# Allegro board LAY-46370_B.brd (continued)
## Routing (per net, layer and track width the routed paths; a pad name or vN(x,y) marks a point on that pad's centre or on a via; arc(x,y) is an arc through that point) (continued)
I2C3_SCL_3V3: length 235.3
  TOP w0.109: v1(31.41,22.55) 30.83,21.97 R291.1 ; U5.8 v1(181.52,100.89) 181.98,100.43 R13.2 182.23,100.09 182.42,99.9 185.02,99.9 187.05,97.88 J21.5
  L6_IN2 w0.114: v1(181.52,100.89) 181.44,100.89 181.08,101.25 177.1,101.25 172.78,96.94 172.78,33.55 170.72,31.48 170.72,31.01 v1(171.19,30.54)
  BOTTOM w0.109: v1(171.19,30.54) 169.63,28.98 121.7,28.98 114.5,21.77 81.51,21.77 80.2,23.08 65.06,23.08 63.74,21.76 32.2,21.76 v1(31.41,22.55)
I2C3_SDA: length 258.8
  TOP w0.102: v1(109.03,117.81) 109.03,125.05 v1(108.97,125.11) R171.2 ; v1(183.15,90.33) 182.83,90.01 R307.1 ; R161.2 85.33,125.67 v1(85.33,125.07) ; R197.1 v1(185.54,31.71)
  TOP w0.109: U5.5 178.94,100.49 v1(178.39,99.93) 177.82,99.37 R10.2 176.95,98.59 176.57,98.21 174.83,98.21 TP8.1 ; v1(101.97,58.32) 101.75,58.32 101.42,58.64 J3.63
  L6_IN2 w0.114: v1(101.97,58.32) 101.95,58.32 101.44,58.83 101.44,65.07 106.75,70.38 106.75,94.49 107.86,95.6 107.86,116.64 v1(109.03,117.81) ; v1(185.54,31.71) 184.88,32.37 184.88,88.6 v1(183.15,90.33) 183.15,97.2 182,98.35 179.98,98.35 v1(178.39,99.93)
  BOTTOM w0.109: v1(109.03,117.81) 109.21,117.81 109.59,117.44 165.61,117.44 178.86,104.2 178.86,100.4 v1(178.39,99.93) ; v1(108.97,125.11) 108.02,126.06 88.4,126.06 86.84,124.51 85.9,124.51 v1(85.33,125.07)
I2C3_SDA_3V3: length 240.6
  TOP w0.109: J21.3 191.9,100.42 193.01,99.3 193.01,97.27 192.75,97 184.01,97 182.23,98.78 R14.2 v1(181.57,100.01) 181.09,100.49 U5.7 ; R292.1 v1(32.37,22.49)
  L6_IN2 w0.114: v1(171.21,31.25) 173.25,33.3 173.25,96.86 177.3,100.91 180.66,100.91 v1(181.57,100.01)
  BOTTOM w0.109: v1(32.37,22.49) 32.82,22.04 63.33,22.04 64.67,23.38 80.46,23.38 81.74,22.1 114.34,22.1 121.61,29.37 169.32,29.37 v1(171.21,31.25)
I2C4_SCL: length 45
  TOP w0.109: v1(101.97,58.93) 101.82,59.07 J3.65
  L6_IN2 w0.114: v1(110.82,95.92) 107.12,92.22 107.12,70.23 101.82,64.93 101.82,59.07 v1(101.97,58.93)
  BOTTOM w0.109: U6.2 111.23,95.51 v1(110.82,95.92) R16.2
I2C4_SDA: length 45.2
  TOP w0.109: v1(102.59,58.91) 102.59,58.95 102.08,59.46 102.08,59.76 102.22,59.9 J3.67
  L6_IN2 w0.114: v1(111.63,95.89) 107.45,91.7 107.45,70.1 102.18,64.83 102.18,59.35 102.59,58.93 v1(102.59,58.91)
  BOTTOM w0.109: U6.3 v1(111.63,95.89) 111.63,96.3 R17.2
I2C5_SCL: length 15.7
  L6_IN2 w0.114: v1(110.45,87.44) 110.45,91.82 112.95,94.32 112.95,95.91 v1(112.71,96.15)
  BOTTOM w0.102: v1(110.45,87.44) 110.93,87.44 111.21,87.16 TP9.1 111.07,86.96 U52.11
  BOTTOM w0.109: R18.2 112.78,96.22 v1(112.71,96.15) 112.7,96.15 112.03,95.48 U6.4
I2C5_SCL_3V3: length 107.2
  TOP w0.109: v1(138.61,95.18) 138.61,99.55 157.24,118.18 190.66,118.18 196.84,124.36 196.84,127.1 R221.1
  BOTTOM w0.109: v1(138.61,95.18) 132.09,95.18 126.94,90.03 113.46,90.03 113.29,90.2 113.29,91.16 113.06,91.39 R22.2 112.03,92 U6.8
I2C5_SDA: length 16.2
  L6_IN2 w0.114: v1(108.17,87.76) 108.17,90.22 112.48,94.53 v1(112.48,95.31)
  BOTTOM w0.102: v1(108.17,87.76) 108.59,87.33 TP10.1 108.59,86.1 109.57,85.11 U52.8 ; U6.5 112.43,95.26 v1(112.48,95.31)
  BOTTOM w0.109: v1(112.48,95.31) 113.23,95.31 113.97,96.05 R19.2
I2C5_SDA_3V3: length 108.3
  TOP w0.109: R222.1 197.2,129.32 197.2,124.3 190.73,117.83 157.29,117.83 139.32,99.86 v1(139.32,95.2)
  BOTTOM w0.109: v1(139.32,95.2) 138.9,95.62 132.01,95.62 127.78,91.39 R23.2 112.43,92.78 U6.7
ILIM_5V_VBUS: length 2.2
  TOP w0.109: U11.6 32.59,20.73 TP20.1
ILIM_5V_VBUS1: length 1.7
  TOP w0.203: TP29.1 45.27,28.96 U17.6
IOEXP_NINT: length 1.8
  TOP w0.102: U1.22 182.15,88.41 R308.2
IOEXP_SCL: length 1.8
  TOP w0.102: R306.2 183.65,88.56 U1.19
IOEXP_SDA: length 1.8
  TOP w0.102: R307.2 183.15,88.52 U1.20
JTAG_MOD: length 6
  TOP w0.102: J1.66 v1(83.89,111.74) 84.52,112.37 84.52,115.13 TP122.1
  BOTTOM w0.102: v1(83.89,111.74) 83.85,111.78 R313.1
JTAG_RESET: length 118.6
  TOP w0.109: J24.10 18.68,133.14 D23.C 16.36,132.39 16.76,131.98 R245.2 ; D26.C 20.83,28.58 v1(20.58,28.83)
  L6_IN2 w0.114: J24.10 20.66,133.62 22.79,133.62 25.04,131.37 25.04,119.19 25.52,118.71 25.52,74.62 25.04,74.14 25.04,47.86 20.58,43.41 v1(20.58,28.83)
JTAG_TCK: length 134.7
  TOP w0.109: v1(16.09,83.55) 17.06,84.53 55.59,84.53 69.63,98.57 69.63,112.25 73.96,116.59 84.52,116.59 85.19,115.92 85.19,112.46 84.29,111.56 J1.68
  L6_IN2 w0.114: v1(16.09,83.55) 15.96,83.42 15.96,54.73 11.64,50.41 10.36,50.41 v1(9.93,49.98)
  BOTTOM w0.109: v1(9.93,49.98) 9.52,49.57 U8.2
JTAG_TDI: length 132.6
  TOP w0.109: v1(16.78,83.52) 17.32,84.06 55.65,84.06 69.92,98.32 69.92,112.11 74.1,116.29 81.87,116.29 83.4,114.76 83.4,111.32 83.49,111.24 J1.64
  L6_IN2 w0.114: v1(16.78,83.52) 16.41,83.15 16.41,54.62 9.83,48.04 v1(9.83,47.96)
  BOTTOM w0.109: U8.5 9.64,48.16 v1(9.83,47.96)
JTAG_TDO: length 138
  TOP w0.109: J1.62 83.1,110.66 83.1,111.06 83.13,111.1 83.13,114.57 81.66,116.04 74.36,116.04 70.19,111.87 70.19,98.15 55.76,83.72 18.35,83.72 v1(18.09,83.46)
  L6_IN2 w0.114: v1(18.09,83.46) 18.04,83.46 17.91,83.34 17.91,53.87 10.56,46.51 v1(10.38,46.51)
  BOTTOM w0.109: U8.10 7.12,49.17 6.56,48.61 6.56,47.79 8.15,46.19 10.06,46.19 v1(10.38,46.51)
JTAG_TMS: length 134.7
  TOP w0.109: v1(17.46,83.49) 17.46,83.32 17.81,82.97 18.45,82.97 18.9,83.43 55.91,83.43 70.46,97.98 70.46,111.73 74.47,115.74 81.54,115.74 82.88,114.4 82.88,111.24 82.69,111.05 J1.60
  L6_IN2 w0.114: v1(10.43,47.93) 11.5,47.93 17.46,53.89 17.46,82.67 17.46,82.67 v1(17.46,83.49)
  BOTTOM w0.109: U8.7 8.03,47.26 8.39,46.91 9.4,46.91 v1(10.43,47.93)
LD1_I2C_SCL: length 2.7
  TOP w0.203: R61.2 62.06,31.48 60.39,33.15 U14.B1
LD1_I2C_SDA: length 2.4
  TOP w0.203: U14.C1 60.5,33.55 61.46,32.58 R62.2
LD1_NINT: length 25.1
  TOP w0.109: R60.2 41.45,27.34 R63.2 41.46,27.36 v1(41.46,28.1)
  TOP w0.203: v1(61.02,33.84) 60.91,33.95 U14.D1
  BOTTOM w0.109: v1(41.46,28.1) 42.92,29.56 46.4,29.56 47.08,28.88 53.79,28.88 58.74,33.84 v1(61.02,33.84)
LED0/CFG_EXT: length 7.9
  TOP w0.102: R86.2 R92.1
  TOP w0.109: R92.1 96.14,34.67 96.25,34.57 96.25,32.46 98.65,30.06 U23.32
LED1/CFGLDO0: length 43
  TOP w0.109: C82.1 R94.1 v1(96.2,31.7) 96.36,31.7 98.41,29.66 U23.33
  L6_IN2 w0.114: v1(96.2,31.7) 96.6,31.31 96.6,29.94 95.34,28.69 95.34,13.75 104.82,4.27 107.5,4.27 J8.14
LED2/CFGLDO1: length 36.2
  TOP w0.109: C83.1 R87.2 ; C83.1 R93.1 ; C83.1 v1(96.08,30.26) 96.63,29.71 97.76,29.71 98.21,29.26 U23.34
  L6_IN2 w0.114: J8.12 98.93,3.13 98.93,9.52 94.94,13.51 94.94,29.11 v1(96.08,30.26)
LVDS0_CLK_N: length 70.5
  TOP w0.091: J15.A2 139.24,133.05 138.91,133.38 138.91,133.66 139.05,133.81 139.98,133.81 142.13,131.66 142.13,127.06 141.89,126.82 U40.10 U40.1 141.89,125.36 142.13,125.12 142.13,124.69 139.73,122.3 132.62,122.3 v1(132.52,122.4) ; v1(104.34,106.25) 104.12,106.25 103.87,106.5 103.87,106.93 103.93,106.99 J2.47
  L3_IN1 w0.084: v1(104.34,106.25) 104.23,106.14 103.92,106.14 103.79,106.01 103.66,105.87 103.66,104.78 106.26,102.18 118.36,102.18 134.06,117.88 134.06,121.4 133.16,122.3 132.64,122.3 132.54,122.4 v1(132.52,122.4)
LVDS0_CLK_P: length 70.7
  TOP w0.091: v1(132.54,121.81) 132.54,121.83 132.74,122.03 139.84,122.03 142.39,124.58 U40.2 U40.9 142.39,131.77 140.09,134.07 138.94,134.07 138.63,133.76 138.63,133.28 138.44,133.08 J15.A3 ; v1(104.37,105.66) 104.09,105.66 103.6,106.15 103.6,106.93 103.53,106.99 J2.45
  L3_IN1 w0.084: v1(132.54,121.81) 132.76,122.03 133.05,122.03 133.79,121.29 133.79,117.99 118.25,102.45 106.37,102.45 103.92,104.9 103.92,105.76 103.98,105.82 104.2,105.82 v1(104.37,105.66)
LVDS0_TS_SCL: length 3.7
  TOP w0.102: J15.B11 132.44,127.14 R172.1
LVDS0_TS_SDA: length 3.5
  TOP w0.102: J15.B10 133.24,126.84 R170.1
LVDS0_TX0_N: length 67.9
  TOP w0.091: J2.35 101.53,106.99 101.47,106.93 101.47,106.48 101.7,106.25 v1(101.92,106.25) ; v1(138.88,124.39) 138.88,124.4 138.84,124.44 U41.10 U41.1 138.84,126.94 139.64,127.74 J15.B2
  L3_IN1 w0.084: v1(101.92,106.25) 101.77,106.09 101.53,106.09 101.25,105.81 101.25,104.8 105.41,100.63 119.83,100.63 138.78,119.59 138.78,119.82 138.87,119.91 139.86,119.91 140.11,120.16 140.11,120.56 139.86,120.8 138.87,120.8 138.78,120.89 138.78,121.07 138.87,121.16 139.83,121.16 140.08,121.4 140.08,121.8 139.83,122.05 138.87,122.05 138.78,122.13 138.78,122.31 138.87,122.4 139.82,122.4 140.06,122.64 140.06,123.05 139.82,123.29 138.87,123.29 138.78,123.38 138.78,124.29 v1(138.88,124.39)
LVDS0_TX0_P: length 67.9
  TOP w0.091: v1(138.29,124.39) 138.29,124.41 138.58,124.69 138.58,125.1 138.34,125.33 U41.9 U41.2 138.34,126.82 139.37,127.85 139.37,128.58 139.27,128.68 138.99,128.68 138.84,128.83 J15.B3 ; J2.33 101.13,106.99 101.2,106.93 101.2,106.37 101.9,105.66 v1(101.94,105.66)
  L3_IN1 w0.084: v1(138.29,124.39) 138.51,124.17 138.51,123.27 138.76,123.02 139.71,123.02 139.79,122.94 139.79,122.75 139.71,122.67 138.76,122.67 138.51,122.42 138.51,122.02 138.76,121.78 139.72,121.78 139.81,121.69 139.81,121.51 139.72,121.42 138.76,121.42 138.51,121.18 138.51,120.78 138.76,120.53 139.75,120.53 139.84,120.45 139.84,120.27 139.75,120.18 138.76,120.18 138.51,119.93 138.51,119.7 119.72,100.9 105.52,100.9 101.51,104.91 101.51,105.7 101.64,105.82 101.77,105.82 101.92,105.66 v1(101.94,105.66)
LVDS0_TX1_N: length 67.8
  TOP w0.091: J15.B5 137.24,128.8 137.34,128.7 U41.4 U41.7 137.34,124.44 v1(137.39,124.4) ; J2.41 102.73,106.99 102.71,106.97 102.71,106.47 102.93,106.25 v1(103.13,106.25)
  L3_IN1 w0.084: v1(137.39,124.4) 137.31,124.32 137.31,123.72 137.29,123.7 137.29,123.7 137.04,123.46 135.51,123.46 135.42,123.37 135.42,123.19 135.51,123.1 137.04,123.1 137.29,122.86 137.29,122.46 137.04,122.21 135.41,122.21 135.32,122.12 135.32,121.95 135.41,121.86 137.04,121.86 137.29,121.61 137.29,121.21 137.04,120.97 135.41,120.97 135.32,120.88 135.32,120.7 135.41,120.61 137.04,120.61 137.29,120.37 137.29,119.72 118.91,101.34 105.9,101.34 102.47,104.77 102.47,105.59 103.12,106.25 v1(103.13,106.25)
LVDS0_TX1_P: length 67.7
  TOP w0.091: v1(136.8,124.4) 136.8,124.44 137.02,124.66 137.02,125.17 136.84,125.35 U41.6 U41.5 136.84,127 137.08,127.23 137.08,128.55 136.91,128.72 136.59,128.72 136.44,128.87 J15.B6 ; J2.39 102.33,106.99 102.44,106.89 102.44,106.36 102.77,106.03 102.77,105.91 103.01,105.66 v1(103.14,105.66)
  L3_IN1 w0.084: v1(136.8,124.4) 137.02,124.18 137.02,123.81 136.93,123.72 135.4,123.72 135.16,123.48 135.16,123.08 135.4,122.84 136.93,122.84 137.02,122.75 137.02,122.57 136.93,122.48 135.3,122.48 135.05,122.23 135.05,121.84 135.3,121.59 136.93,121.59 137.02,121.5 137.02,121.32 136.93,121.24 135.3,121.24 135.05,120.99 135.05,120.59 135.3,120.35 136.93,120.35 137.02,120.26 137.02,119.83 118.8,101.61 106.01,101.61 102.73,104.88 102.73,105.48 102.91,105.66 v1(103.14,105.66)
LVDS0_TX2_N: length 67.8
  TOP w0.091: J2.53 105.13,106.99 105.11,106.97 105.11,106.59 105.45,106.25 v1(105.55,106.25) ; v1(130.12,124.41) 130.12,124.43 130.02,124.52 130.02,125 130.09,125.07 U42.10 U42.1 130.09,126.92 130.84,127.66 J15.B13
  L3_IN1 w0.084: v1(105.55,106.25) 105.23,106.25 104.86,105.87 104.86,104.76 106.44,103.18 117.88,103.18 130.02,115.32 130.02,115.76 130.11,115.85 130.69,115.85 130.94,116.09 130.94,116.55 130.69,116.8 130.11,116.8 130.02,116.89 130.02,117.3 130.11,117.39 131.83,117.39 132.08,117.63 132.08,118.03 131.83,118.28 130.11,118.28 130.02,118.36 130.02,118.54 130.11,118.63 131.83,118.63 132.08,118.88 132.08,119.28 131.83,119.52 130.11,119.52 130.02,119.61 130.02,119.79 130.11,119.88 131.83,119.88 132.08,120.12 132.08,120.52 131.83,120.77 130.11,120.77 130.02,120.85 130.02,121.03 130.11,121.12 131.47,121.12 131.71,121.37 131.71,121.76 131.47,122.01 130.11,122.01 130.02,122.1 130.02,122.28 130.11,122.37 131.47,122.37 131.71,122.61 131.71,123.01 131.47,123.25 130.11,123.25 130.02,123.34 130.02,124.31 v1(130.12,124.41)
LVDS0_TX2_P: length 67.9
  TOP w0.091: J15.B14 130.04,128.95 130.28,128.7 130.48,128.7 130.57,128.61 130.57,127.79 129.59,126.81 U42.2 U42.9 129.59,125.33 129.75,125.17 129.75,124.63 129.53,124.41 v1(129.53,124.41) ; v1(105.55,105.66) 105.43,105.66 105.18,105.91 105.18,106.01 104.84,106.36 104.84,106.89 104.73,106.99 J2.51
  L3_IN1 w0.084: v1(105.55,105.66) 105.36,105.85 105.21,105.85 105.12,105.76 105.12,104.87 106.55,103.44 117.77,103.44 129.75,115.43 129.75,115.87 130,116.11 130.58,116.11 130.67,116.2 130.67,116.44 130.58,116.53 130,116.53 129.75,116.78 129.75,117.41 130,117.65 131.72,117.65 131.81,117.74 131.81,117.92 131.72,118.01 130,118.01 129.75,118.25 129.75,118.65 130,118.9 131.72,118.9 131.81,118.99 131.81,119.16 131.72,119.25 130,119.25 129.75,119.5 129.75,119.9 130,120.14 131.72,120.14 131.81,120.23 131.81,120.41 131.72,120.5 130,120.5 129.75,120.74 129.75,121.14 130,121.39 131.36,121.39 131.45,121.48 131.45,121.65 131.36,121.74 130,121.74 129.75,121.99 129.75,122.39 130,122.63 131.36,122.63 131.44,122.72 131.44,122.9 131.36,122.99 130,122.99 129.75,123.23 129.75,124.19 v1(129.53,124.41)
LVDS0_TX3_N: length 67.8
  TOP w0.091: J15.B16 128.44,128.91 128.59,128.76 U42.4 U42.7 128.59,124.5 v1(128.66,124.43) ; J2.59 106.33,106.99 106.27,106.93 106.27,106.46 106.51,106.21 106.64,106.21 106.67,106.25 v1(106.75,106.25)
  L3_IN1 w0.084: v1(128.66,124.43) 128.66,123.16 128.41,122.91 126.85,122.91 126.76,122.83 126.76,122.64 126.85,122.55 128.39,122.55 128.63,122.31 128.63,121.91 128.39,121.67 126.82,121.67 126.73,121.58 126.73,121.4 126.82,121.31 128.41,121.31 128.66,121.06 128.66,120.67 128.41,120.42 126.82,120.42 126.73,120.33 126.73,120.15 126.82,120.07 128.41,120.07 128.66,119.82 128.66,119.42 128.41,119.18 126.82,119.18 126.73,119.09 126.73,118.91 126.82,118.82 128.41,118.82 128.66,118.58 128.66,118.18 128.41,117.93 126.82,117.93 126.73,117.84 126.73,117.66 126.82,117.58 128.41,117.58 128.66,117.33 128.66,116.93 128.41,116.69 126.82,116.69 126.73,116.6 126.73,116.42 126.82,116.33 128.41,116.33 128.66,116.09 128.66,115.31 127.83,114.48 127.49,114.48 127.11,114.85 126.99,114.85 126.86,114.73 126.86,114.6 127.23,114.23 127.23,113.88 117.52,104.17 106.55,104.17 106.06,104.67 106.06,105.88 106.3,106.13 106.63,106.13 v1(106.75,106.25)
LVDS0_TX3_P: length 67.8
  TOP w0.091: J2.57 105.93,106.99 106,106.93 106,106.35 106.61,105.73 106.68,105.66 v1(106.75,105.66) ; J15.B17 127.64,128.95 127.87,128.72 128.09,128.72 128.33,128.49 128.33,127.07 128.09,126.84 U42.5 U42.6 128.09,125.16 128.29,124.96 128.29,124.66 128.29,124.65 v1(128.07,124.43)
  L3_IN1 w0.084: v1(128.07,124.43) 128.07,124.35 128.26,124.17 128.3,124.17 128.39,124.08 128.39,123.27 128.3,123.18 126.74,123.18 126.5,122.94 126.5,122.53 126.74,122.29 128.27,122.29 128.36,122.2 128.36,122.02 128.27,121.93 126.71,121.93 126.46,121.69 126.46,121.29 126.71,121.04 128.3,121.04 128.39,120.95 128.39,120.78 128.3,120.69 126.71,120.69 126.46,120.44 126.46,120.04 126.71,119.8 128.3,119.8 128.39,119.71 128.39,119.53 128.3,119.44 126.71,119.44 126.46,119.2 126.46,118.8 126.71,118.55 128.3,118.55 128.39,118.47 128.39,118.29 128.3,118.2 126.71,118.2 126.46,117.95 126.46,117.55 126.71,117.31 128.3,117.31 128.39,117.22 128.39,117.04 128.3,116.95 126.71,116.95 126.46,116.71 126.46,116.31 126.71,116.06 128.3,116.06 128.39,115.98 128.39,115.42 127.72,114.75 127.6,114.75 127.22,115.12 126.88,115.12 126.6,114.84 126.6,114.49 126.97,114.12 126.97,113.99 117.41,104.44 106.66,104.44 106.32,104.78 106.32,105.77 106.41,105.86 106.55,105.86 v1(106.75,105.66)
LVDS1_CLK_N: length 53.2
  TOP w0.091: J2.17 97.93,106.99 97.89,106.95 97.89,106.2 97.34,105.65 v1(97.18,105.65) ; v1(117.8,124.51) 117.8,124.55 118.02,124.77 118.02,125.17 117.87,125.32 U43.1 U43.10 117.87,132.58 117.26,133.19 117.13,133.19 116.81,132.87 116.69,132.87 116.56,133 116.56,133.13 116.88,133.44 116.88,133.57 116.57,133.88 115.73,133.88 115.24,133.39 J16.A2
  L3_IN1 w0.084: v1(97.18,105.65) 97.29,105.77 97.59,105.77 97.91,106.08 97.91,107.08 99.88,109.06 101.33,109.06 103.11,110.85 103.11,119.73 104.61,121.23 114.83,121.23 116.2,122.6 116.2,124.86 116.84,125.5 117.73,125.5 118.07,125.17 118.07,124.85 117.8,124.58 v1(117.8,124.51)
LVDS1_CLK_P: length 53.2
  TOP w0.091: v1(118.38,124.51) 118.29,124.6 118.29,125.22 118.37,125.3 U43.2 U43.9 118.37,126.86 118.14,127.09 118.14,132.69 116.68,134.14 115.61,134.14 114.44,132.97 J16.A3 ; J2.15 97.53,106.99 97.62,106.91 97.62,106.31 97.42,106.11 97.29,106.11 v1(97.16,106.24)
  L3_IN1 w0.084: v1(118.38,124.51) 118.38,125.23 117.84,125.77 116.73,125.77 115.93,124.97 115.93,122.71 114.72,121.5 104.5,121.5 102.84,119.84 102.84,110.96 101.21,109.33 99.77,109.33 97.64,107.2 97.64,106.19 97.49,106.04 97.36,106.04 v1(97.16,106.24)
LVDS1_TS_SCL: length 3.5
  TOP w0.102: R173.1 108.44,127.01 J16.B11
LVDS1_TS_SDA: length 3.4
  TOP w0.102: R171.1 109.24,126.74 J16.B10
LVDS1_TX0_N: length 52
  TOP w0.091: J2.5 95.53,106.99 95.48,106.94 95.48,106.09 95.19,105.8 94.87,105.8 v1(94.73,105.66) ; v1(114.77,124.51) 114.72,124.56 U44.10 U44.1 114.72,127.27 115.51,128.06 115.51,128.86 115.64,129 J16.B2
  L3_IN1 w0.084: v1(114.77,124.51) 114.65,124.39 114.65,124 114.26,123.61 112.71,123.61 112.13,124.19 104.13,124.19 103.88,124.44 103.88,126.01 103.77,126.12 103.21,126.12 103.1,126.01 103.1,124.68 102.85,124.44 102.09,124.44 101.85,124.68 101.85,126.11 101.76,126.2 101.14,126.2 101.05,126.11 101.05,111.88 99.75,110.58 97.56,110.58 95.51,108.53 95.51,106.06 95.21,105.76 94.83,105.76 v1(94.73,105.66)
LVDS1_TX0_P: length 51.9
  TOP w0.091: v1(94.68,106.25) 94.69,106.25 94.87,106.07 95.08,106.07 95.21,106.2 95.21,107 95.13,107.08 J2.3 ; J16.B3 114.84,129.1 115.24,128.71 115.24,128.17 114.45,127.38 114.45,127.04 114.22,126.8 U44.2 U44.9 114.22,125.31 114.41,125.12 114.41,124.73 114.19,124.51 v1(114.09,124.51)
  L3_IN1 w0.084: v1(114.09,124.51) 114.21,124.51 114.34,124.39 114.34,124.06 114.15,123.88 112.82,123.88 112.24,124.46 104.24,124.46 104.15,124.55 104.15,126.12 103.88,126.39 103.1,126.39 102.83,126.12 102.83,124.79 102.74,124.71 102.2,124.71 102.11,124.79 102.11,126.23 101.87,126.47 101.03,126.47 100.78,126.23 100.78,111.99 99.64,110.85 97.45,110.85 95.24,108.64 95.24,106.17 95.1,106.03 94.95,106.03 94.73,106.25 v1(94.68,106.25)
LVDS1_TX1_N: length 52.2
  TOP w0.091: v1(95.95,105.66) 96,105.66 96.67,106.33 96.67,106.93 96.73,106.99 J2.11 ; J16.B5 113.24,126.96 113.22,126.93 U44.4 U44.7 113.22,125.07 113.16,125.01 113.16,123.23 v1(113.26,123.14)
  L3_IN1 w0.084: v1(113.26,123.14) 113.17,123.05 113.17,122.64 112.69,122.16 111.35,122.16 111.11,122.41 111.11,123.03 111.02,123.12 110.83,123.12 110.75,123.03 110.75,122.41 110.51,122.16 110.11,122.16 109.86,122.41 109.86,123.04 109.75,123.15 109.62,123.15 109.51,123.04 109.51,122.41 109.26,122.16 108.86,122.16 108.62,122.41 108.62,123.04 108.5,123.15 108.38,123.15 108.26,123.04 108.26,122.41 108.02,122.16 107.62,122.16 107.37,122.41 107.37,123.04 107.26,123.15 107.13,123.15 107.02,123.04 107.02,122.41 106.77,122.16 106.37,122.16 106.13,122.41 106.13,123.04 106.01,123.15 105.89,123.15 105.77,123.04 105.77,122.41 105.53,122.16 105.13,122.16 104.88,122.41 104.88,123.04 104.77,123.15 104.64,123.15 104.53,123.04 104.53,122.36 104.26,122.09 103.91,122.09 103.64,122.36 103.64,123.04 103.52,123.15 103.4,123.15 103.28,123.04 103.28,122.41 103.04,122.16 102,122.16 101.91,122.07 101.91,110.76 100.99,109.84 99.01,109.84 96.71,107.53 96.71,106.12 96.43,105.84 96.12,105.84 v1(95.95,105.66)
LVDS1_TX1_P: length 52.1
  TOP w0.091: J2.9 96.33,106.99 96.4,106.93 96.4,106.44 96.2,106.25 v1(95.95,106.25) ; v1(112.67,123.14) 112.67,123.14 112.89,123.36 112.89,125.15 112.72,125.33 U44.6 U44.5 112.72,126.81 112.98,127.07 112.98,127.14 112.84,127.28 112.84,127.44 112.98,127.58 112.98,127.81 112.89,127.89 112.82,127.89 112.73,127.98 112.73,128.16 112.82,128.25 112.89,128.25 112.98,128.34 112.98,128.64 112.86,128.76 112.69,128.76 112.44,129 J16.B6
  L3_IN1 w0.084: v1(95.95,106.25) 96.06,106.14 96.35,106.14 96.44,106.23 96.44,107.65 98.9,110.1 100.88,110.1 101.64,110.87 101.64,122.18 101.89,122.43 102.93,122.43 103.02,122.52 103.02,123.15 103.29,123.42 103.63,123.42 103.91,123.15 103.91,122.47 104.02,122.35 104.15,122.35 104.26,122.47 104.26,123.15 104.53,123.42 104.88,123.42 105.15,123.15 105.15,122.52 105.24,122.43 105.42,122.43 105.51,122.52 105.51,123.15 105.78,123.42 106.12,123.42 106.4,123.15 106.4,122.52 106.48,122.43 106.66,122.43 106.75,122.52 106.75,123.15 107.02,123.42 107.37,123.42 107.64,123.15 107.64,122.52 107.73,122.43 107.91,122.43 108,122.52 108,123.15 108.27,123.42 108.61,123.42 108.88,123.15 108.88,122.52 108.97,122.43 109.15,122.43 109.24,122.52 109.24,123.15 109.51,123.42 109.86,123.42 110.13,123.15 110.13,122.52 110.22,122.43 110.4,122.43 110.48,122.52 110.48,123.14 110.72,123.38 111.13,123.38 111.37,123.14 111.37,122.52 111.46,122.43 112.58,122.43 112.89,122.74 112.89,122.92 v1(112.67,123.14)
LVDS1_TX2_N: length 53.2
  TOP w0.091: v1(104.84,119.4) 104.84,119.4 104.84,119.53 104.92,119.62 107.45,119.62 108.34,120.51 108.34,122.23 106.25,124.33 U45.10 U45.1 106.25,126.92 106.65,127.33 106.65,128.76 106.84,128.95 J16.B13 ; v1(98.37,105.66) 98.37,105.66 99.07,106.36 99.07,107.21 99.13,107.28 J2.23
  L3_IN1 w0.084: v1(98.37,105.66) 98.49,105.79 98.85,105.79 99.11,106.04 99.11,107.02 100.4,108.31 102.1,108.31 104.02,110.23 104.02,112.29 104.11,112.38 105.86,112.38 106.1,112.62 106.1,113.02 105.86,113.27 104.11,113.27 104.02,113.36 104.02,113.53 104.11,113.62 105.86,113.62 106.1,113.87 106.1,114.27 105.86,114.51 104.11,114.51 104.02,114.6 104.02,114.78 104.11,114.87 105.86,114.87 106.1,115.11 106.1,115.51 105.86,115.76 104.11,115.76 104.02,115.85 104.02,116.02 104.11,116.11 105.86,116.11 106.1,116.36 106.1,116.76 105.86,117 104.11,117 104.02,117.09 104.02,117.27 104.11,117.36 105.6,117.36 105.87,117.63 105.87,117.97 105.6,118.25 104.11,118.25 104.02,118.33 104.02,119.21 104.37,119.56 104.64,119.56 104.8,119.4 v1(104.84,119.4)
LVDS1_TX2_P: length 53.2
  TOP w0.091: v1(104.8,120.05) 104.98,119.88 107.34,119.88 108.08,120.62 108.08,122.12 105.98,124.22 105.98,125.12 105.75,125.35 U45.9 U45.2 105.75,127.07 105.95,127.27 106.22,127.27 106.39,127.44 106.39,127.9 106.3,127.99 106.1,127.99 106.01,128.08 106.01,128.25 106.1,128.34 106.3,128.34 106.39,128.43 106.39,128.67 106.33,128.73 106.13,128.73 106.04,128.82 J16.B14 ; J2.21 98.73,107.22 98.8,107.16 98.8,106.47 98.58,106.25 v1(98.35,106.25)
  L3_IN1 w0.084: v1(104.8,120.05) 104.58,119.83 104.26,119.83 103.75,119.32 103.75,118.22 104,117.98 105.49,117.98 105.61,117.86 105.61,117.74 105.49,117.62 104,117.62 103.75,117.38 103.75,116.98 104,116.73 105.75,116.73 105.83,116.65 105.83,116.47 105.75,116.38 104,116.38 103.75,116.13 103.75,115.73 104,115.49 105.75,115.49 105.83,115.4 105.83,115.22 105.75,115.13 104,115.13 103.75,114.89 103.75,114.49 104,114.24 105.75,114.24 105.83,114.16 105.83,113.98 105.75,113.89 104,113.89 103.75,113.64 103.75,113.25 104,113 105.75,113 105.83,112.91 105.83,112.73 105.75,112.64 104,112.64 103.75,112.4 103.75,110.34 101.99,108.58 100.29,108.58 98.84,107.13 98.84,106.15 98.75,106.07 98.54,106.07 v1(98.35,106.25)
LVDS1_TX3_N: length 52.6
  TOP w0.091: J2.29 100.33,106.99 100.27,106.93 100.27,106.37 99.56,105.66 v1(99.55,105.66) ; v1(106.9,120.68) 106.73,120.85 106.73,122.04 104.75,124.02 U45.7 U45.4 104.75,128.64 104.44,128.95 J16.B16
  L3_IN1 w0.084: v1(106.9,120.68) 106.75,120.54 106.75,119.03 107.34,118.44 107.34,116.66 107.43,116.57 110.47,116.57 110.71,116.33 110.71,115.93 110.47,115.69 107.43,115.69 107.34,115.6 107.34,115.42 107.43,115.33 110.5,115.33 110.74,115.08 110.74,114.69 110.5,114.44 107.43,114.44 107.34,114.35 107.34,114.17 107.43,114.08 110.5,114.08 110.74,113.84 110.74,113.44 110.5,113.2 107.43,113.2 107.34,113.11 107.34,110.11 104.71,107.48 100.66,107.48 100.31,107.13 100.31,106.11 100.03,105.83 99.72,105.83 v1(99.55,105.66)
LVDS1_TX3_P: length 52.7
  TOP w0.091: v1(106.31,120.68) 106.31,120.7 106.46,120.85 106.46,121.93 104.48,123.91 104.48,125.12 104.25,125.36 U45.6 U45.5 104.25,126.87 104.48,127.1 104.48,127.76 104.39,127.85 104.22,127.85 104.13,127.94 104.13,128.11 104.22,128.2 104.39,128.2 104.48,128.29 104.48,128.53 104.31,128.71 104.05,128.71 103.64,129.11 J16.B17 ; J2.27 99.93,106.99 100,106.93 100,106.48 99.76,106.25 v1(99.54,106.25)
  L3_IN1 w0.084: v1(99.54,106.25) 99.68,106.11 99.93,106.11 100.04,106.22 100.04,107.24 100.55,107.74 104.6,107.74 107.07,110.22 107.07,113.22 107.32,113.46 110.39,113.46 110.48,113.55 110.48,113.73 110.39,113.82 107.32,113.82 107.07,114.06 107.07,114.46 107.32,114.71 110.39,114.71 110.48,114.8 110.48,114.97 110.39,115.06 107.32,115.06 107.07,115.31 107.07,115.71 107.32,115.95 110.36,115.95 110.45,116.04 110.45,116.22 110.36,116.31 107.32,116.31 107.07,116.55 107.07,118.33 106.48,118.92 106.48,120.51 v1(106.31,120.68)
LVDS_BL_PWM: length 74.6
  TOP w0.102: v1(134.6,125.08) 134.84,125.32 J15.B8 ; v1(75.09,113.51) J1.22 ; R168.2 v1(111.1,125.04)
  BOTTOM w0.102: v1(75.09,113.51) 75.09,113.9 78.32,117.13 100.26,117.13 107.04,123.91 109.97,123.91 v1(111.1,125.04)
  BOTTOM w0.109: v1(134.6,125.08) 133.12,123.6 127.75,123.6 125.68,125.67 111.7,125.67 111.1,125.07 v1(111.1,125.04)
LVDS_EN: length 84.9
  TOP w0.102: J1.26 75.89,111.09 75.96,111.15 75.96,113.26 v1(75.73,113.49)
  TOP w0.33: J15.A11 v1(132.04,133.56) ; J16.A11 v1(108.04,133.56)
  L6_IN2 w0.114: v1(74.39,131.77) 74.44,131.72 74.44,114.78 75.73,113.5 v1(75.73,113.49)
  BOTTOM w0.109: v1(74.39,131.77) 106.12,131.77 107.91,133.56 v1(108.04,133.56) 108.35,133.25 108.35,132.45 109.26,131.54 130.02,131.54 v1(132.04,133.56)
LVDS_TS_NINT: length 74.5
  TOP w0.102: J1.18 74.29,111.16 74.16,111.29 74.16,113.37 v1(74.29,113.49) ; v1(133.96,125.15) 134.04,125.23 J15.B9 ; R169.2 v1(110.04,125.07)
  BOTTOM w0.102: v1(74.29,113.49) 78.37,117.57 100.23,117.57 106.92,124.26 109.23,124.26 v1(110.04,125.07)
  BOTTOM w0.109: v1(110.04,125.07) 111.01,126.04 125.77,126.04 127.92,123.89 132.71,123.89 v1(133.96,125.15)
LVL_SHF_TCK: length 5.1
  BOTTOM w0.109: U7.10 12.19,49.54 11.25,50.48 9.77,50.48 9.26,49.97 U8.1
LVL_SHF_TDI: length 4.6
  BOTTOM w0.109: U7.9 10.88,49.14 10.51,48.77 U8.4
LVL_SHF_TDO: length 11.8
  BOTTOM w0.109: U7.7 12.83,48.34 10.35,45.86 8.01,45.86 6.24,47.62 6.24,49 6.81,49.57 U8.11
LVL_SHF_TMS: length 8
  BOTTOM w0.109: U8.8 7.63,47.16 8.29,46.5 9.73,46.5 11.97,48.74 U7.8
M2_BT_WAKE: length 5.6
  BOTTOM w0.102: J10.20 158.97,88.05 159.1,87.92 D6.C 158.28,86.47 157.49,87.26 R149.2
M2_BT_WAKE_HOST: length 86.6
  TOP w0.109: v1(116.22,97.02) 116.12,97.02 113.53,99.61 J2.95
  L6_IN2 w0.114: v1(142.1,97.08) 141.34,96.32 141.34,72.07 v1(142.38,71.03)
  BOTTOM w0.109: D6.A 146.21,71.03 v1(142.38,71.03) ; v1(116.22,97.02) 116.45,97.26 141.91,97.26 v1(142.1,97.08)
M2_DIS1: length 2.9
  BOTTOM w0.102: J10.56 149.97,88.76 R32.1
M2_DIS2: length 5.2
  TOP w0.102: v1(150.47,90.92) 150.47,89.92 TP39.1
  TOP w0.109: v1(150.47,90.92) 151.23,91.68 R142.1
  BOTTOM w0.102: J10.54 v1(150.47,90.92)
M2_I2C_SCL: length 4.2
  BOTTOM w0.102: J10.60 148.97,89 148.26,88.29 147.22,88.29 R153.1
M2_I2C_SDA: length 3.7
  BOTTOM w0.102: R152.1 147.64,87.66 148.13,87.66 149.47,89 J10.58
M2_LED1#: length 2.3
  TOP w0.102: D30.C 162.47,87.94 v1(162.47,88.53)
  BOTTOM w0.102: J10.6 v1(162.47,88.53)
M2_LED2#: length 2.4
  TOP w0.102: v1(160.22,88.41) 160.22,88.04 D31.C
  BOTTOM w0.102: J10.16 159.97,88.66 v1(160.22,88.41)
M2_PCM_CLK: length 62.7
  TOP w0.109: J4.11 116.63,64.2 116.64,64.21 146.55,64.21 160.58,78.24 v1(160.58,78.4)
  BOTTOM w0.102: J10.8 161.97,88.18 162.21,87.94 162.21,80.03 v1(160.58,78.4)
M2_PCM_IN: length 62.2
  TOP w0.109: J4.17 116.42,65.41 116.57,65.26 145.17,65.26 159.24,79.33 160.04,79.33 v1(160.37,79.01)
  BOTTOM w0.102: J10.12 160.97,88.67 161.86,87.79 161.86,80.36 160.51,79.01 v1(160.37,79.01)
M2_PCM_OUT: length 61.5
  TOP w0.109: J4.15 145.79,65 v1(159.62,78.83)
  BOTTOM w0.102: v1(159.62,78.83) 159.62,78.87 161.57,80.83 161.57,87.67 160.47,88.77 J10.14
M2_PCM_SYNC: length 75.7
  TOP w0.102: J4.13 115.25,64.6 114.68,65.17 114.68,81.95 115.78,83.05 115.78,88.4 v1(116.24,88.86)
  BOTTOM w0.109: J10.10 161.47,90.68 158.01,94.14 132.71,94.14 127.42,88.86 v1(116.24,88.86)
M2_PERST: length 2.9
  BOTTOM w0.102: R31.1 150.97,88.69 J10.52
M2_SD_CLK: length 59.8
  TOP w0.102: J2.75 v1(109.53,106.83)
  BOTTOM w0.109: J10.9 161.72,100.33 157.05,105 119.99,105 116.94,108.06 110.63,108.06 109.53,106.96 v1(109.53,106.83)
M2_SD_CMD: length 60.4
  TOP w0.102: v1(109.52,106.21) 109.64,106.21 109.96,106.54 109.96,107.13 109.93,107.16 J2.77
  BOTTOM w0.109: J10.11 161.22,100.38 156.88,104.71 119.74,104.71 116.65,107.8 110.76,107.8 109.97,107 109.97,106.53 109.69,106.25 109.56,106.25 v1(109.52,106.21)
M2_SD_DATA0: length 58.7
  TOP w0.102: v1(110.42,106.1) 110.49,106.1 110.89,106.51 110.89,107.05 110.73,107.2 J2.81
  BOTTOM w0.109: J10.13 160.72,100.37 157.56,103.53 156.4,103.53 155.59,104.34 119.6,104.34 116.41,107.53 111.98,107.53 110.55,106.1 v1(110.42,106.1)
M2_SD_DATA1: length 59.1
  TOP w0.102: v1(110.47,105.42) 111.13,106.08 J2.83
  BOTTOM w0.109: v1(110.47,105.42) 110.94,105.89 110.94,106.12 112.1,107.29 116.21,107.29 119.4,104.09 155.27,104.09 156.22,103.14 157.49,103.14 160.22,100.4 J10.15
M2_SD_DATA2: length 58.2
  TOP w0.102: J2.85 111.53,106.09 v1(111.81,105.82)
  BOTTOM w0.109: J10.17 159.72,98.65 159.83,98.76 159.84,98.76 159.95,98.87 159.95,99.08 159.84,99.19 159.83,99.19 159.72,99.3 159.72,99.52 159.83,99.63 159.84,99.63 159.95,99.74 159.95,99.96 159.84,100.07 159.83,100.07 159.72,100.18 159.72,100.44 157.78,102.38 157.63,102.38 157.24,101.99 156.95,101.99 155.15,103.79 119.18,103.79 116.6,106.37 116.09,106.37 115.98,106.48 115.98,106.87 115.87,106.98 115.65,106.98 115.54,106.87 115.54,106.48 115.43,106.37 113.98,106.37 113.87,106.48 113.87,106.77 113.76,106.88 113.54,106.88 113.43,106.77 113.43,106.48 113.32,106.37 112.23,106.37 111.81,105.95 v1(111.81,105.82)
M2_SD_DATA3: length 59
  TOP w0.102: J2.87 111.93,107.23 111.9,107.2 111.9,106.61 112.33,106.18 112.33,105.9 v1(112.4,105.83)
  BOTTOM w0.109: J10.19 159.22,99.36 158.89,99.69 158.89,99.83 159.26,100.2 159.26,100.34 159.12,100.49 158.97,100.49 158.6,100.12 158.46,100.12 158.32,100.26 158.32,100.41 158.69,100.78 158.69,100.92 158.54,101.06 158.4,101.06 158.03,100.69 157.89,100.69 157.74,100.84 157.74,100.98 158.11,101.35 158.11,101.49 157.97,101.64 157.82,101.64 157.45,101.27 157.31,101.27 155.1,103.48 118.95,103.48 116.32,106.11 113.61,106.11 113.48,105.98 113.48,105.32 113.38,105.23 113.18,105.23 113.07,105.33 113.07,105.97 112.93,106.11 112.51,106.11 112.4,106 v1(112.4,105.83)
M2_SD_NRST: length 58.1
  TOP w0.102: v1(109.59,105.62) 109.77,105.44 109.77,105.11 109.67,105.01 109.14,105.01 109.04,105.11 109.04,107.1 109.13,107.2 J2.73
  BOTTOM w0.109: J10.23 158.22,99.43 154.71,102.94 118.56,102.94 116.71,104.79 109.56,104.79 109.28,105.07 109.28,105.52 109.38,105.62 v1(109.59,105.62)
M2_SD_WAKE_HOST: length 58.2
  TOP w0.102: v1(114.15,105.4) 114.02,105.4 113.92,105.5 113.92,105.86 114.02,105.96 116.93,105.96 117.03,106.06 117.03,106.27 116.93,106.37 114.03,106.37 113.93,106.47 J2.97
  BOTTOM w0.109: J10.21 158.72,99.38 154.88,103.22 118.71,103.22 116.53,105.4 115.87,105.4 115.77,105.5 115.77,105.73 115.67,105.84 114.26,105.84 114.15,105.73 v1(114.15,105.4)
M2_UART_CTS: length 68.6
  TOP w0.109: TP119.1 152.74,85.61 v1(152.74,85.66) ; v1(99.46,65.42) 99.51,65.42 99.94,64.99 99.94,63.9 99.82,63.79 J3.56
  BOTTOM w0.102: R372.2 v1(152.74,85.66)
  BOTTOM w0.109: v1(152.74,85.66) 152.1,85.02 152.1,81.36 143.66,72.92 107.65,72.92 100.73,66 100.04,66 v1(99.46,65.42)
M2_UART_RTS: length 68.4
  TOP w0.109: J3.58 100.22,63.77 100.18,63.81 v1(100.18,65.46) ; v1(153.83,85.67) 153.51,85.35 TP118.1
  BOTTOM w0.102: v1(153.83,85.67) R371.2
  BOTTOM w0.109: v1(100.18,65.46) 100.25,65.39 100.66,65.39 107.95,72.68 144.31,72.68 153.83,82.2 v1(153.83,85.67)
M2_UART_RXD: length 71.2
  TOP w0.109: J3.54 99.42,64.13 v1(99.49,64.2) ; TP116.1 156.12,85.67 v1(156.01,85.67)
  BOTTOM w0.102: v1(156.01,85.67) R369.2
  BOTTOM w0.109: v1(99.49,64.2) 99.93,64.63 100.79,64.63 108.36,72.21 114.69,72.21 115.42,71.48 144.6,71.48 155.43,82.31 155.43,85.1 v1(156.01,85.67)
M2_UART_TXD: length 70.5
  TOP w0.109: v1(154.92,85.67) 155.42,85.18 TP117.1 ; v1(99.45,64.82) 99.21,64.82 99.02,64.63 J3.52
  BOTTOM w0.102: R370.2 v1(154.92,85.67)
  BOTTOM w0.109: v1(154.92,85.67) 154.92,82.54 144.12,71.75 116.05,71.75 115.36,72.44 108.2,72.44 100.71,64.96 99.59,64.96 v1(99.45,64.82)
M2_USB_DN: length 97
  TOP w0.102: TP38.1 162.72,99.37 v1(162.72,98.92)
  BOTTOM w0.102: J10.5 v1(162.72,98.92) 162.88,99.08 162.88,103.47 160.76,105.59 120.34,105.59 115.38,110.55 115.38,111.7 113.14,113.94 94.5,113.94 89.16,108.61 81.94,108.61 81.64,108.9 81.64,109.58 R301.2
M2_USB_DP: length 97
  TOP w0.102: v1(163.31,98.93) 163.31,99.37 TP37.1
  BOTTOM w0.102: J10.3 163.22,98.85 v1(163.31,98.93) 163.09,99.14 163.09,103.56 160.85,105.8 120.43,105.8 115.59,110.64 115.59,111.79 113.23,114.16 94.41,114.16 89.07,108.82 82.03,108.82 81.86,108.99 81.86,109.7 R300.2
MICBIAS: length 4
  TOP w0.203: R199.1 196.79,26.95 C174.1 195.42,28.32 U50.1
NAND_DQS: length 46.3
  TOP w0.102: v1(108.32,112.05) 108.41,112.05 108.8,111.66 108.8,111.26 108.73,111.19 J2.72
  L6_IN2 w0.114: v1(114.61,88.43) 115.11,88.93 115.11,100.61 111.13,104.6 111.13,109.24 v1(108.32,112.05)
  BOTTOM w0.109: v1(114.61,88.43) 115.88,87.16 130.62,87.16 130.85,86.93 U3.8
NX5P_EN: length 2
  TOP w0.203: R302.2 58.83,24.05 U22.B4
NX5P_FLT#: length 2.3
  TOP w0.203: R448.2 58.3,23.5 U22.A4
NX5P_FRS: length 1.8
  TOP w0.203: U22.C4 59.33,24.68 R68.2
NX5P_ILIM: length 1.8
  TOP w0.203: U22.A3 58.18,23 57.53,23.64 R67.2
NX20P_ACK: length 4.6
  TOP w0.203: U9.A2 26.8,25.19 R43.1 25.79,27.19 TP13.1
NX20P_EN: length 5.8
  TOP w0.203: Q1.3 25.79,22.4 R42.2 ; R42.2 27.94,24.04 U9.A3 ; R42.2 C164.1
NX20P_OVLO: length 1.6
  TOP w0.203: U9.B3 29.09,24.69 R44.1
ONOFF: length 296.4
  TOP w0.109: TP120.1 196.27,138.42 v1(195.48,139.21) 195.4,139.29 SW1.3 SW1.4
  TOP w0.203: J2.74 109.13,111.89 109.53,112.29 109.53,117.44 v1(109.97,117.88)
  L6_IN2 w0.114: v1(123.95,48.67) 123.95,76.19 122.86,77.28 122.86,97.53 115.72,104.67 115.72,112.12 v1(109.97,117.88)
  BOTTOM w0.109: v1(123.95,48.67) 123.95,48.68 36.19,48.68 31.55,53.31 R381.2
  BOTTOM w0.203: v1(109.97,117.88) 175.47,117.88 195.48,137.89 v1(195.48,139.21)
P0_0: length 2.6
  BOTTOM w0.109: R386.1 10.16,72.21 U70.1
P0_1: length 2.4
  BOTTOM w0.109: R387.1 10.66,72.83 U70.2
P0_2: length 2.3
  BOTTOM w0.109: U70.3 11.16,72.08 11.34,72.25 R388.1
P0_3: length 2.6
  BOTTOM w0.109: U70.4 11.66,71.88 12.47,72.68 R389.1
P0_4: length 2.8
  BOTTOM w0.109: R390.1 12.16,71.84 U70.5
P0_5: length 3
  BOTTOM w0.109: R391.1 12.66,71.22 U70.6
P0_6: length 3.9
  BOTTOM w0.109: R392.1 13.37,70.84 U70.7
P0_7: length 3.4
  BOTTOM w0.109: U70.8 13.94,69.82 14.38,70.26 14.38,70.75 R393.1
P1_0: length 3.6
  BOTTOM w0.109: U70.10 14.53,68.82 14.99,69.29 14.99,70.28 R394.1
P1_1: length 3.5
  BOTTOM w0.102: R415.2 15.6,69.76 R395.1
  BOTTOM w0.109: R415.2 14.95,68.65 14.62,68.32 U70.11
P1_2: length 3.4
  BOTTOM w0.102: R416.2 15.6,66.47 R396.1
  BOTTOM w0.109: R396.1 14.79,67.55 14.51,67.82 U70.12
P1_3: length 4.5
  BOTTOM w0.102: R397.1 R417.2
  BOTTOM w0.109: R397.1 13.07,67.12 U70.13
P1_4: length 3.6
  BOTTOM w0.102: R398.1 R418.2
  BOTTOM w0.109: U70.14 12.16,66.13 12.59,65.7 12.59,65.42 R418.2
P1_5: length 3.3
  BOTTOM w0.102: R419.2 R399.1
  BOTTOM w0.109: R419.2 11.94,65.62 11.66,65.9 U70.15
P1_6: length 3.8
  BOTTOM w0.102: R420.2 8.67,64.99 R400.1
  BOTTOM w0.109: R400.1 11.16,66.39 U70.16
P1_7: length 37.5
  TOP w0.102: v1(35.16,66.65) 35.16,65.97 R421.2
  TOP w0.109: R421.2 33.98,65.93 R401.1
  BOTTOM w0.109: U70.17 10.66,66.29 10.09,65.72 8.57,65.72 8.01,65.16 8.01,63.46 8.82,62.64 23.85,62.64 24.84,63.63 33.58,63.63 33.95,64 33.95,65.44 v1(35.16,66.65)
PCIE_CLKN: length 88.7
  TOP w0.099: R132.2 154.95,110.66 R136.1
  TOP w0.114: J1.53 81.49,107 81.53,106.96 81.53,106.39 82.26,105.66 v1(82.32,105.66) ; R136.1 153.84,110.66 153.84,111.08 153.74,111.18 152.09,111.18 149.61,108.71 149.61,100.51 149.66,100.47 v1(149.66,100.3)
  BOTTOM w0.114: v1(82.32,105.66) 82.65,105.66 82.68,105.64 82.79,105.64 82.85,105.57 82.85,104.44 85.04,102.25 114.58,102.25 117.36,99.47 149.25,99.47 149.51,99.73 149.51,100.15 v1(149.66,100.3)
PCIE_CLKP: length 88.5
  TOP w0.099: R135.1 154.96,111.94 R131.2
  TOP w0.114: v1(149.07,100.3) 149.07,100.46 149.39,100.78 149.39,108.8 151.99,111.41 153.74,111.41 153.84,111.51 R135.1 ; v1(82.29,106.25) 82.06,106.25 81.76,106.55 81.76,107.05 81.77,107.06 81.77,107.14 81.89,107.26 J1.55
  BOTTOM w0.114: v1(82.29,106.25) 82.39,106.25 82.77,105.87 82.88,105.87 83.08,105.67 83.08,104.53 85.13,102.48 114.67,102.48 117.46,99.69 149.15,99.69 149.28,99.82 149.28,100.11 149.09,100.3 v1(149.07,100.3)
PCIE_DIG1: length 24.9
  TOP w0.254: C349.1 155.56,102.75 U81.6 ; U29.7 161.2,112.35 v1(161.32,112.47)
  TOP w0.381: R129.2 162.2,113.43 R130.2 162.19,113.34 v1(161.32,112.47) ; C349.1 155.42,101.63 154.43,102.62 154.43,106.28 v1(155.53,107.37)
  BOTTOM w0.381: v1(161.32,112.47) 161.63,112.17 C102.1 160.57,111.8 C103.1 160.57,112.89 159.98,113.48 156.45,113.48 155.53,112.56 v1(155.53,107.37)
PCIE_NCLKREQ_3V3: length 61.7
  TOP w0.102: v1(150.72,95.92) 152.77,95.92 TP98.1
  TOP w0.109: TP98.1 153.07,95.91 157.7,100.54 R144.1 157.17,103.07 156.96,103.28 U81.2
  BOTTOM w0.102: J10.53 v1(150.72,95.92)
  BOTTOM w0.109: v1(150.72,95.92) 149.22,94.42 132.43,94.42 127.41,89.39 110.73,89.39 110.42,89.7 110.42,91.16 110.2,91.38 R20.2 111.23,92.67 U6.10
PCIE_NDIS_3V3: length 20.8
  TOP w0.102: TP101.1 138.02,83.88 v1(137.23,84.67)
  TOP w0.109: TP101.1 146.8,83.88 v1(148.61,85.69)
  BOTTOM w0.102: R33.1 137.22,80.26 138.07,81.11 138.07,84.14 137.54,84.67 v1(137.23,84.67) 137.13,84.67 136.88,84.93 U3.21 ; R32.2 v1(148.61,85.69)
PCIE_NRST_3V3: length 16
  TOP w0.102: v1(137.27,85.3) 138.77,85.3 TP100.1
  TOP w0.109: TP100.1 139.4,84.68 146.9,84.68 148.4,86.19 149.11,86.19 v1(149.65,85.65)
  BOTTOM w0.102: v1(137.27,85.3) 137.15,85.43 U3.20 ; R31.2 v1(149.65,85.65)
PCIE_NWAKE_3V3: length 47.4
  BOTTOM w0.109: J10.55 150.22,95.98 148.93,94.7 132.11,94.7 127.04,89.63 110.86,89.63 110.68,89.81 110.68,91.23 110.84,91.39 R21.2 111.63,91.87 U6.9
PCIE_REQ: length 23.9
  TOP w0.109: R140.1 R144.2 ; R140.1 155.9,104.86 155.53,104.5 U81.4 ; R140.1 158.07,104.86 v1(158.5,104.43) ; R139.1 158.39,115.29 158.12,115.56 156.21,115.56 154.39,113.74 v1(154.22,113.74)
  L6_IN2 w0.114: v1(154.22,113.74) 153.66,113.18 153.66,107.37 156,105.04 157.89,105.04 v1(158.5,104.43)
PCIE_RXN: length 77.5
  TOP w0.114: J1.59 82.69,107 82.71,106.98 82.71,106.39 83.43,105.66 v1(83.53,105.66)
  BOTTOM w0.114: v1(83.53,105.66) 83.66,105.8 83.95,105.8 84.09,105.65 84.09,104.42 85.45,103.06 115.28,103.06 117.51,100.83 151.55,100.83 153.36,99.02 153.36,98.38 153.22,98.24 J10.43
PCIE_RXP: length 77.4
  TOP w0.114: J1.61 83.09,107.14 82.95,107 82.95,106.55 83.25,106.25 v1(83.51,106.25)
  BOTTOM w0.114: v1(83.51,106.25) 83.74,106.02 84.04,106.02 84.31,105.75 84.31,104.53 85.55,103.29 115.37,103.29 117.61,101.05 151.65,101.05 153.58,99.11 153.58,98.38 153.72,98.24 J10.41
PCIE_TXN: length 75.9
  TOP w0.114: J1.65 83.89,107.15 83.95,107.09 83.95,106.27 84.57,105.64 v1(84.75,105.64)
  BOTTOM w0.114: C121.1 154.75,100.91 154.75,101.31 154.25,101.81 118.14,101.81 116,103.95 85.96,103.95 85.22,104.68 85.22,105.69 85.13,105.78 84.86,105.78 84.75,105.67 v1(84.75,105.64)
PCIE_TXP: length 75.9
  TOP w0.114: v1(84.72,106.22) 84.58,106.08 84.45,106.08 84.2,106.33 84.2,107.01 84.29,107.1 J1.67
  BOTTOM w0.114: C120.1 154.98,100.98 154.98,101.4 154.35,102.04 118.24,102.04 116.09,104.18 86.05,104.18 85.44,104.78 85.44,105.84 85.23,106.06 84.88,106.06 v1(84.72,106.22)
PD1_I2C_SCL: length 25.9
  TOP w0.109: R58.2 65.13,29 63.63,27.5 v1(63.63,27.27) ; v1(44.12,28.8) 44.47,28.45 U17.8
  BOTTOM w0.109: v1(44.12,28.8) 45.43,27.49 63.4,27.49 v1(63.63,27.27)
PD1_I2C_SDA: length 27.2
  TOP w0.109: v1(64.21,27.28) 65.6,28.66 65.6,32.12 R59.2 ; v1(44.74,28.81) 44.87,28.68 U17.7
  BOTTOM w0.109: v1(64.21,27.28) 64.21,27.56 64.02,27.75 45.81,27.75 v1(44.74,28.81)
PD_EN_SNK: length 26.5
  TOP w0.109: Q2.1 49.26,22.69 48.62,22.69 v1(45.2,19.27) ; v1(34.27,17.76) 34.11,17.92 U11.2 ; R2.1 v1(26.66,18.18)
  BOTTOM w0.102: v1(26.66,18.18) 27.08,17.76 v1(34.27,17.76)
  BOTTOM w0.109: v1(34.27,17.76) 43.69,17.76 v1(45.2,19.27)
PD_EN_SNK1: length 4.8
  TOP w0.109: R64.1 49.77,26.48 48.43,25.14 48.06,25.14 46.88,26.33 U17.2
PD_EN_SRC: length 2.1
  TOP w0.109: U11.16 32.59,16.1 33.23,15.46 TP17.1
PD_EN_SRC1: length 31.1
  TOP w0.102: v1(45.97,25.3) 45.8,25.48 U17.16
  TOP w0.109: v1(64.86,27.17) 65.91,28.22 65.91,33.34 63.75,35.49 R55.1
  BOTTOM w0.109: v1(45.97,25.3) 46.27,25.01 54.47,25.01 55.21,25.75 61.04,25.75 62.05,26.76 64.44,26.76 v1(64.86,27.17)
PD_I2C_SCL: length 2.1
  TOP w0.109: U11.8 31.79,20.21 R291.2
PD_I2C_SDA: length 1.8
  TOP w0.109: U11.7 32.19,20.91 R292.2
PDM/CAN2_SEL: length 69.5
  TOP w0.102: v1(130.23,59.35) 130.71,58.87 130.71,58.51 130.56,58.36 U54.10
  TOP w0.109: v1(130.29,69.81) 145.68,69.81 160.13,84.26 176.11,84.26 176.81,83.55 179.05,83.55 179.16,83.66 R445.1 179.92,84.97 U1.4
  L6_IN2 w0.114: v1(130.29,69.81) 130.23,69.75 v1(130.23,59.35)
PDM_CLK: length 16.4
  TOP w0.109: U58.10 194.13,49.89 195.63,51.38 J21.40
PDM_STREAM_0: length 13.1
  TOP w0.109: U57.10 185.25,58.41 185.3,58.46 193.18,58.46 194.4,57.24 J21.38
PDM_STREAM_1: length 7.9
  TOP w0.109: U57.9 186.05,58.01 186.82,57.24 J21.37
PDM_STREAM_2: length 14
  TOP w0.102: v1(193.3,59.77) 193.3,59.78 J21.36
  TOP w0.109: v1(183.97,57.49) 183.85,57.61 U57.8
  BOTTOM w0.109: v1(183.97,57.49) 186.84,60.36 192.7,60.36 v1(193.3,59.77)
PDM_STREAM_3: length 8.9
  TOP w0.102: J21.35 v1(188.34,59.78)
  TOP w0.109: v1(183.97,56.87) 183.63,57.21 U57.7
  BOTTOM w0.109: v1(183.97,56.87) 186.88,59.78 v1(188.34,59.78)
PER_12V: length 11.8
  TOP w0.254: TP105.1 v1(23.54,120.84)
  TOP w0.33: J15.A9 v1(133.64,133.56) ; J16.A9 v1(109.64,133.56) ; J16.A8 v1(110.44,133.56) ; J15.A8 v1(134.44,133.56)
  BOTTOM w0.381: 29.03,103.75 29.04,103.74 29.04,101.2 28.66,100.81 C280.1 27.2,99.72 R276.1
PER_12V_PG: length 3.7
  BOTTOM w0.203: U49.6 20.3,99.51 20.24,99.45 R282.2 19.4,100.57 TP81.1
PMIC_32K_OUT: length 58
  TOP w0.102: v1(97.1,59.47) 97.03,59.54 97.03,60.28 J3.41
  BOTTOM w0.109: v1(97.1,59.47) 96.77,59.8 96.77,64.77 99.38,67.38 100.54,67.38 107.44,74.28 107.44,87.81 108.56,88.92 113.03,88.92 116.52,85.43 R314.1
PMIC_ON_REQ: length 76
  TOP w0.102: J2.78 109.93,111.5 v1(110.64,112.21)
  TOP w0.109: v1(52.46,112.22) 60.51,112.22 65.61,117.33 104.49,117.33 108.96,112.86 v1(108.96,112.73)
  L6_IN2 w0.114: v1(52.46,101.19) v1(52.46,112.22) ; v1(110.64,112.21) 109.48,112.21 v1(108.96,112.73)
  BOTTOM w0.102: R265.1 v1(52.46,101.19)
PMIC_SCLH: length 7
  TOP w0.109: TP54.1 98.99,56.15 98.99,59.92 99.02,59.95 J3.51
PMIC_SCLL: length 6.4
  TOP w0.109: J3.45 97.82,54.77 TP52.1
PMIC_SDAH: length 7.5
  TOP w0.109: J3.53 99.42,59.87 99.25,59.7 99.25,57.17 TP55.1
PMIC_SDAL: length 6.9
  TOP w0.109: TP53.1 98.07,55.8 98.07,59.68 98.22,59.83 J3.47
POR_B: length 298.3
  TOP w0.102: J2.76 109.53,111.9 111.58,113.95 v1(111.58,114.77)
  TOP w0.109: U2.2 177.17,89.02 176.46,88.3 176.46,87.76 v1(176.9,87.32) R407.1
  TOP w0.254: R238.1 20.36,29.68 D26.A v1(21.83,30.15)
  L6_IN2 w0.114: v1(114.45,23.97) 116.73,23.97 122.82,30.06 122.82,48.5 123.44,49.12 123.44,75.89 122.44,76.88 122.44,97.36 115.42,104.38 115.42,111.27 111.92,114.77 v1(111.58,114.77)
  BOTTOM w0.109: v1(114.45,23.97) 112.91,22.42 82.13,22.42 80.83,23.72 64.51,23.72 63.14,22.35 44.43,22.35 36.62,30.15 v1(21.83,30.15) ; v1(176.9,87.32) 181.4,91.82 181.4,94.48 176.45,99.42 169.37,99.42 162.41,106.38 132.34,106.38 123.57,115.16 111.97,115.16 v1(111.58,114.77)
POR_B_INVERT: length 7
  TOP w0.203: R435.1 13.55,32.65 14.37,33.47 17.42,33.47 17.75,33.14 U78.4 17.76,32.07 R431.2
PWM4_3V3: length 25
  TOP w0.254: v1(183.84,48.68) 183.83,48.69 U58.7
  TOP w0.381: v1(197.94,64.86) 197.94,64.86 J21.32
  BOTTOM w0.381: v1(183.84,48.68) 183.84,49.21 197.94,63.31 v1(197.94,64.86)
PWR_MEAS_IO1: length 210.8
  TOP w0.109: v1(180.3,81.66) 180.44,81.81 U1.6 ; J25.15 29.55,51.73 v1(34.18,47.1)
  L6_IN2 w0.114: v1(178.55,40.67) 178.55,62.08 179.92,63.45 179.92,79.95 180.77,80.8 180.77,81.19 v1(180.3,81.66)
  BOTTOM w0.109: v1(178.55,40.67) 178.08,40.19 173.78,40.19 172.08,38.48 162.86,38.48 159.29,42.05 148.51,42.05 146.67,43.88 132.79,43.88 130.89,41.98 96.15,41.98 91.87,46.26 73.52,46.26 72.64,45.38 35.91,45.38 v1(34.18,47.1)
PWR_MEAS_IO2: length 208.8
  TOP w0.109: v1(180.33,81.01) 180.73,81.41 180.73,82.6 181.15,83.01 U1.7 ; v1(34.15,47.77) 29.84,52.08 29.84,59.79 29.95,59.91 J25.17
  L6_IN2 w0.114: v1(177.87,40.68) 177.87,62.36 179.55,64.04 179.55,80.22 v1(180.33,81.01)
  BOTTOM w0.109: v1(34.15,47.77) 36.06,45.85 72.44,45.85 73.18,46.59 91.91,46.59 96.26,42.24 130.78,42.24 132.68,44.14 146.78,44.14 148.62,42.31 159.4,42.31 162.89,38.82 171.88,38.82 173.74,40.68 v1(177.87,40.68)
REF_CLK_32K: length 2.9
  BOTTOM w0.102: R315.2 130.16,85.43 R314.2 130.16,85.43 U3.5
REF_CLK_32K_3V3: length 1.3
  BOTTOM w0.102: U3.19 136.72,85.93 R30.2
REF_CLKN_CN: length 21.7
  TOP w0.099: R136.2 v1(152.52,110.66)
  TOP w0.102: R138.2 154.72,108.47 v1(154.29,108.47)
  TOP w0.114: v1(151.65,98.9) 151.84,98.71 151.84,98.14 152.22,97.75 153.08,97.75 153.47,98.15 153.47,108.47 153.68,108.68 154.06,108.68 v1(154.29,108.47)
  BOTTOM w0.099: v1(154.29,108.47) 154.11,108.65 153.64,108.65 153.39,108.89 153.39,110.96 153.25,111.1 152.62,111.1 152.52,111 v1(152.52,110.66) ; v1(151.65,98.9) 151.86,98.69 151.86,98.38 151.72,98.24 J10.49
REF_CLKP_CN: length 21.5
  TOP w0.099: R135.2 v1(152.48,111.94)
  TOP w0.102: v1(154.26,109.1) 154.72,109.1 R137.2
  TOP w0.114: v1(154.26,109.1) 154.09,108.9 153.59,108.9 153.24,108.56 153.24,98.24 152.98,97.98 152.31,97.98 152.06,98.23 152.06,98.72 v1(152.24,98.9)
  BOTTOM w0.099: J10.47 152.22,98.24 152.08,98.38 152.08,98.69 152.24,98.85 v1(152.24,98.9) ; v1(154.26,109.1) 154.26,108.99 154.14,108.87 153.73,108.87 153.62,108.99 153.62,111.06 153.35,111.33 152.58,111.33 152.48,111.43 v1(152.48,111.94)
REG_FT_1V8: length 4.4
  TOP w0.254: v1(8.23,25.57) 8.23,25.45 7.98,25.2 U60.49
  BOTTOM w0.381: v1(8.23,25.57) 8.28,25.62 C294.1 9,26.73 C295.1 9,26.74 L24.2
REMOTE_SEL: length 50.2
  L6_IN2 w0.114: v1(22.06,57.93) 22.35,58.21 v1(22.35,65.48) 21.62,66.21 21.62,73.48 v1(20.71,74.38)
  BOTTOM w0.102: R351.1 24.46,67.17 R39.2 23.75,65.48 v1(22.35,65.48)
  BOTTOM w0.109: v1(20.71,74.38) 20.71,74.52 20.23,75 20.23,75.22 R458.1 19.6,75.85 12.75,75.85 11.84,76.77 11.84,77.75 11.62,77.97 U20.15 ; v1(22.06,57.93) 19.17,57.93 18.59,57.35 Q12.1 16,53.83 12.8,53.83 10.22,51.24 8.62,51.24 8.43,51.05 U8.15
REMOTE_SEL_B: length 7.9
  BOTTOM w0.203: U7.12 14.11,50.22 17.2,53.31 R385.2 19.24,53.32 Q12.3
RXC/PHYAD1: length 4.2
  TOP w0.102: R98.1 R77.1
  TOP w0.109: R98.1 100.17,32.62 100.63,32.62 101.09,32.16 101.09,31.69 101.02,31.61 U23.27
RXCTL/PHYAD2: length 3.3
  TOP w0.109: U23.26 101.42,32.39 101.7,32.67 R76.1 R97.1
RXD0/RXDLY: length 6.7
  TOP w0.102: R96.1 103.65,35.76 R89.2
  TOP w0.109: U23.25 101.82,31.89 102.78,32.85 R73.1 102.38,33.26 102.27,33.37 102.27,35.45 R96.1
RXD1/TXDLY: length 7
  TOP w0.102: R95.1 105.82,35.76 R88.2
  TOP w0.109: U23.24 102.22,31.73 103.75,33.27 R72.1 104.24,33.27 104.45,33.49 104.45,34.81 104.75,35.1 R88.2
RXD2/PLLOFF: length 3.6
  TOP w0.109: U23.23 102.62,31.72 103.44,32.54 104.22,32.54 R71.1
RXD2_PLLOFF: length 1.1
  TOP w0.381: R91.2 107.12,36.52 R99.1
RXD3/PHYAD0: length 5.3
  TOP w0.109: R90.2 R75.1 104.98,32.22 103.58,32.22 103.02,31.65 U23.22
S_TXN1: length 1.8
  TOP w0.102: U18.7 47.9,17.25 47.26,16.61 47.12,16.61 C48.2
S_TXN2: length 2.6
  TOP w0.102: C53.2 46.77,18.43 46.97,18.63 47.85,18.63 48.32,18.15 U18.6
S_TXP1: length 1.8
  TOP w0.102: C50.2 47.15,16.22 47.2,16.22 47.82,16.85 U18.8
S_TXP2: length 2.6
  TOP w0.102: C52.2 47,18.86 47.94,18.86 48.72,18.08 U18.5
SAI1_RXC: length 1.8
  TOP w0.109: J3.78 104.22,63.8 104.14,63.89 104.14,64.6 R318.1
SAI1_RXD0: length 45.2
  TOP w0.109: J3.82 105.02,63.84 105.16,63.97 105.16,65.81 106.26,66.91 107.32,66.91 111.13,63.1 111.13,56.71 119.85,47.99 119.85,34.85 119.85,34.85 119.85,32.81 119.62,32.58 U4.7
SAI1_RXD1: length 42.6
  TOP w0.109: J3.84 105.42,63.8 105.47,63.84 105.47,65.62 106.43,66.58 107.14,66.58 110.66,63.06 110.66,56.33 118.53,48.46 U4.9
SAI1_RXFS: length 1.7
  TOP w0.109: J3.76 103.82,64.68 R317.1
SAI2_MCLK: length 60.2
  TOP w0.109: J4.18 113.58,65.41 114.46,64.52 114.46,58.03 117.82,54.67 126.86,54.67 v1(127.11,54.91)
  L6_IN2 w0.114: v1(127.85,88.04) 127.31,87.51 127.31,64.56 127.11,64.35 v1(127.11,54.91)
  BOTTOM w0.102: U3.10 127.97,87.93 v1(127.85,88.04)
SAI2_RXC: length 38
  TOP w0.109: J4.14 112.1,64.6 111.57,64.07 111.57,57.25 120.41,48.42 120.41,32.8 119.79,32.18 U4.6
SAI2_RXFS: length 34.6
  TOP w0.109: J4.12 113.54,64.2 114.04,63.71 114.04,57.84 117.82,54.07 v1(118.47,54.07) ; v1(119.14,34.16) 119.14,32.98 U4.8
  L6_IN2 w0.114: v1(118.47,54.07) 118.47,34.83 v1(119.14,34.16)
SAI3_MCLK: length 100.3
  TOP w0.102: J4.22 112.36,66.2 112.33,66.24 111.39,66.24 v1(111.06,66.57)
  TOP w0.109: R195.1 194.44,35.15 v1(193.94,35.65)
  BOTTOM w0.109: v1(111.06,66.57) 111.27,66.36 127.18,66.36 150.28,43.25 159.88,43.25 163.6,39.53 171.49,39.53 173.51,41.55 186.41,41.55 191.86,36.1 193.69,36.1 193.94,35.85 v1(193.94,35.65)
SAI3_RXD: length 97.3
  TOP w0.102: v1(111.51,67.86) 111.55,67.82 111.55,67.78 111.95,67.37 112.43,67.37 112.47,67.4 J4.28
  TOP w0.109: v1(190.82,38.48) 189.12,36.78 R194.1
  BOTTOM w0.109: v1(111.51,67.86) 111.55,67.82 111.55,67.64 111.79,67.4 112.72,67.4 113.2,66.92 127.58,66.92 148.14,46.36 182.93,46.36 v1(190.82,38.48)
SAI3_TXC: length 92.6
  TOP w0.102: J4.21 116.44,66.2 116.48,66.24 116.86,66.24 v1(117.31,65.79)
  TOP w0.109: R191.1 193.37,35.61 v1(193.35,35.62)
  BOTTOM w0.109: v1(193.35,35.62) 193.33,35.6 191.84,35.6 186.23,41.21 173.58,41.21 171.54,39.17 163.03,39.17 159.49,42.71 150.15,42.71 126.88,65.97 117.5,65.97 v1(117.31,65.79)
